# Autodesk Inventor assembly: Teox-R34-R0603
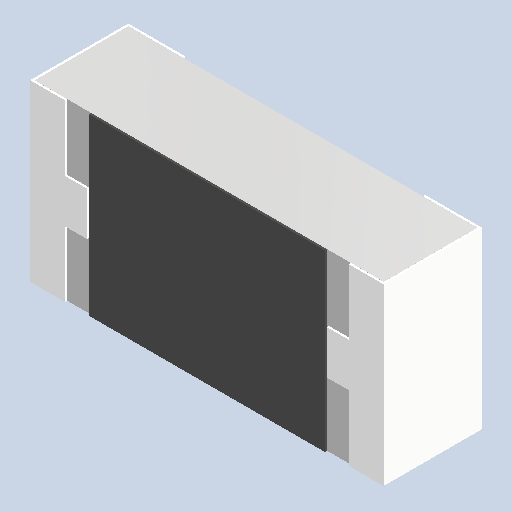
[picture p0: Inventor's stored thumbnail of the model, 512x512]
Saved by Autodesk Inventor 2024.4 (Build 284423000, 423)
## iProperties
Created: 2025-05
Part Number: Teox-R34-R0603
Document SubType Name: Assembly
Designer: AdminForWorker
Title: Teox-R34-R0603
Author: AdminForWorker
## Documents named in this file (2)
- c:\worker\convert-fusion-r02-cosv3\tmp\job-1\2\temp\files\be827049-a7f2-47ea-a815-8d9efd6bfce9\Teox-R34-R0603.iam
- c:\worker\convert-fusion-r02-cosv3\tmp\job-1\2\temp\files\be827049-a7f2-47ea-a815-8d9efd6bfce9\COMPOUND (2).ipt
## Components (1 placed, 1 different names)
1. COMPOUND (2):4
